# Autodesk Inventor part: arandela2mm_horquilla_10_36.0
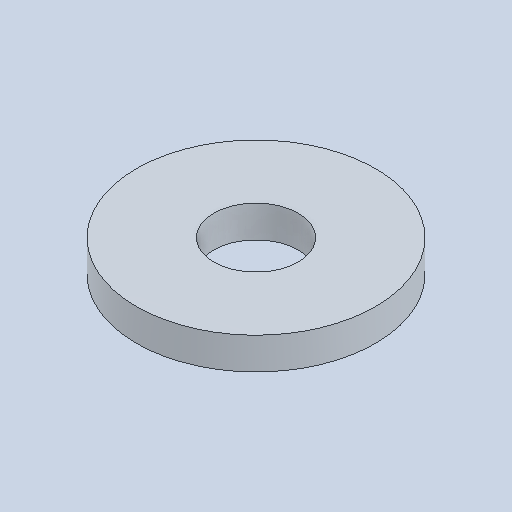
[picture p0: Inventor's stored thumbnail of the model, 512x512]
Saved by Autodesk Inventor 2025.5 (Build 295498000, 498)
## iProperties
Created: 2026-10
Part Number: arandela2mm_horquilla_10_36.0
Material: Genérico
Document SubType Name: Modeling
Designer: Luis M
Density: 1 g/cm^3
Appearance: Valor por defecto
Author: Luis M
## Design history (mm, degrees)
feature "Base1"
node "Sólido1"
